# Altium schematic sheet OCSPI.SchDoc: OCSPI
size A4; Date: Not used; ApprovedBy: Not used; CheckedBy: Not used; Author: Not used; CompanyName: STMicroelectronics; DrawnBy: Not used; Engineer: Not used; Organization: Not used; Address1: Not used; Address2: Not used; Address3: Not used; Address4: Not used; DocumentNumber: Not used; Revision: Not used; SheetNumber: 8; SheetTotal: 23
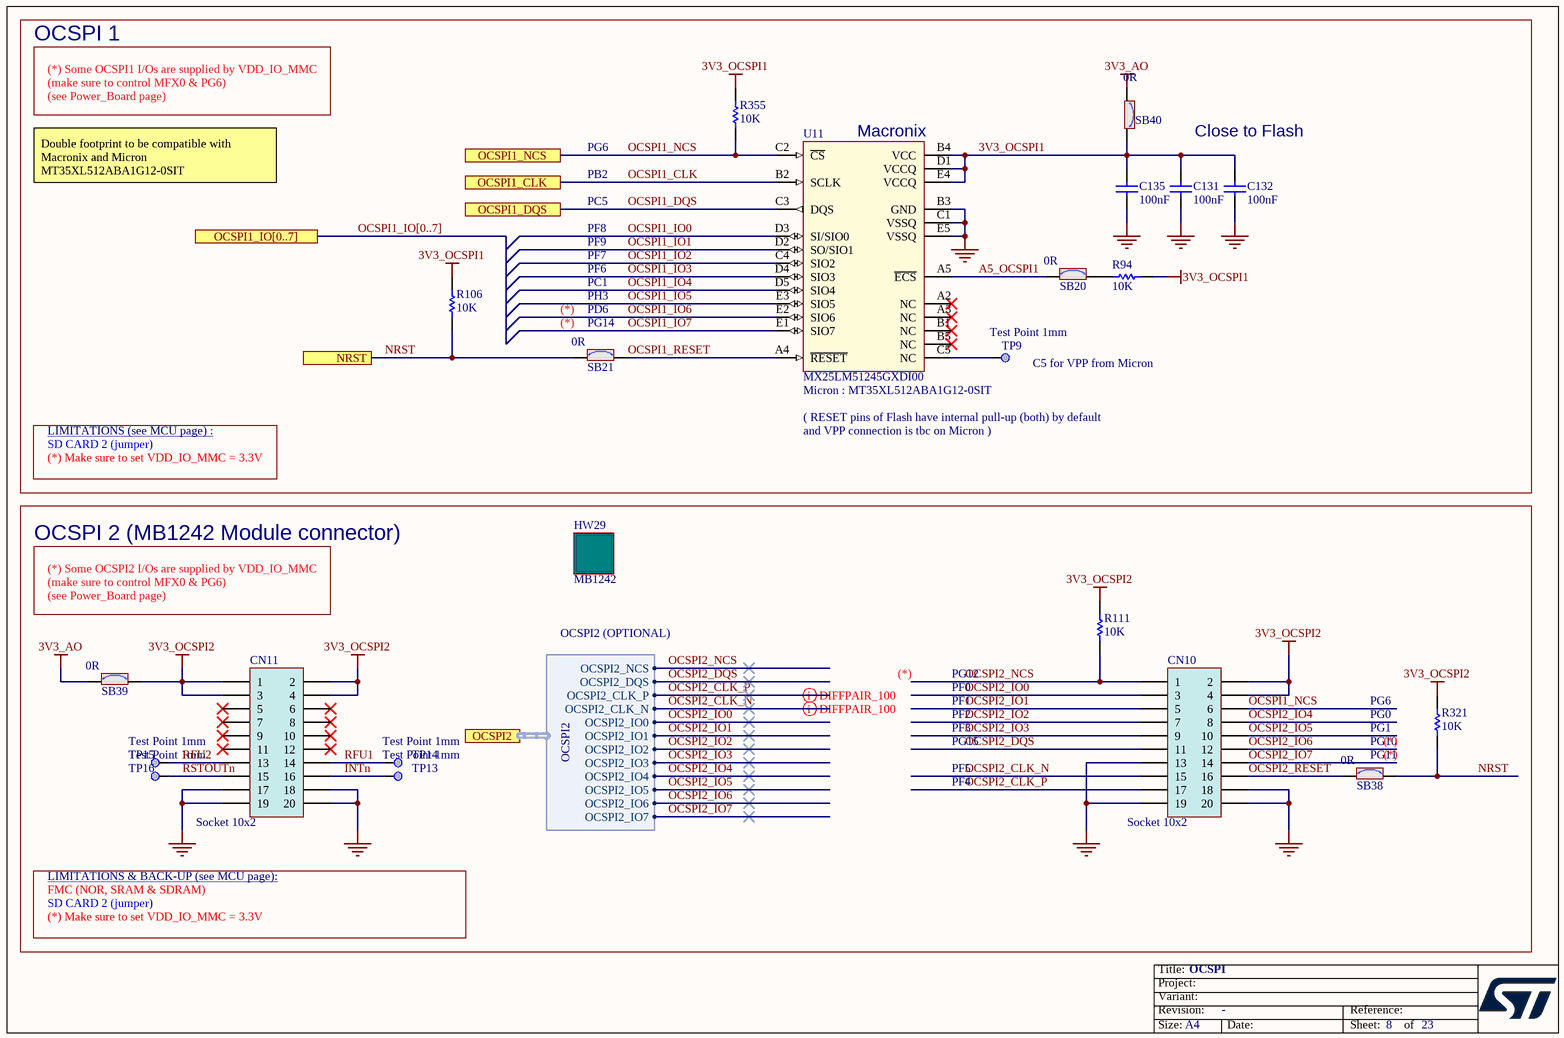
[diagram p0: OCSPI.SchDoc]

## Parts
C131  value 100nF  [C0402]  (hidden comment: Capacitor)
C132  value 100nF  [C0402]  (hidden comment: Capacitor)
C135  value 100nF  [C0402]  (hidden comment: Capacitor)
CN10  Socket 10x2  [CON_SAMTEC_ERF8-010-050-S-DV-TR]
CN11  Socket 10x2  [CON_SAMTEC_ERF8-010-050-S-DV-TR]
HW29  value MB1242  [MOD_ERM8_BGA24-OCTAL-SPI_MB1242]  (hidden comment: Daughter_Board)
R94  value 10K  [R0402]  (hidden comment: Resistor)
R106  value 10K  [R0402]  (hidden comment: Resistor)
R111  value 10K  [R0402]  (hidden comment: Resistor)
R321  value 10K  [R0402]  (hidden comment: Resistor)
R355  value 10K  [R0402]  (hidden comment: Resistor)
SB20  value 0R  [SOLDER-BRIDGE_R0603-0R]  (hidden comment: SB_ON)
SB21  value 0R  [SOLDER-BRIDGE_R0603-0R]  (hidden comment: SB_ON)
SB38  value 0R  [SOLDER-BRIDGE_R0603-0R]  (hidden comment: SB_ON)
SB39  value 0R  [SOLDER-BRIDGE_R0603-0R]  (hidden comment: SB_ON)
SB40  value 0R  [SOLDER-BRIDGE_R0603-0R]  (hidden comment: SB_ON)
TP9  value Test Point 1mm  [TP_SMD_1MM]  (hidden comment: Test Point)  (no BOM)
TP13  value Test Point 1mm  [TP_SMD_1MM]  (hidden comment: Test Point)  (no BOM)
TP14  value Test Point 1mm  [TP_SMD_1MM]  (hidden comment: Test Point)  (no BOM)
TP15  value Test Point 1mm  [TP_SMD_1MM]  (hidden comment: Test Point)  (no BOM)
TP16  value Test Point 1mm  [TP_SMD_1MM]  (hidden comment: Test Point)  (no BOM)
U11  MX25LM51245GXDI00  [ICC_BGA24_5X5-BALL-ARRAY_6X8_P1]

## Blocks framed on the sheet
OCSPI 1: C131 C132 C135 R94 R106 R355 SB20 SB21 SB40 TP9 U11
OCSPI 2 (MB1242 Module connector): CN10 CN11 HW29 R111 R321 SB38 SB39 TP13-TP16

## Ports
NRST, OCSPI1_CLK, OCSPI1_DQS, OCSPI1_IO[0..7], OCSPI1_NCS, OCSPI2 (harness OCSPI2)

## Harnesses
OCSPI2: OCSPI2_NCS, OCSPI2_DQS, OCSPI2_CLK_P, OCSPI2_CLK_N, OCSPI2_IO0, OCSPI2_IO1, OCSPI2_IO2, OCSPI2_IO3, OCSPI2_IO4, OCSPI2_IO5, OCSPI2_IO6, OCSPI2_IO7

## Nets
3V3_AO: SB39.2 SB40.1
3V3_OCSPI1: C131.2 C132.2 C135.2 R94.2 R106.1 R355.1 SB40.2 U11.B4(VCC) U11.D1(VCCQ) U11.E4(VCCQ)
3V3_OCSPI2: CN10.2 CN10.4 CN11.1 CN11.2 CN11.3 CN11.4 R111.1 R321.1 SB39.1
GND: C131.1 C132.1 C135.1 CN10.13 CN10.18 CN10.19 CN10.20 CN11.17 CN11.18 CN11.19 CN11.20 U11.B3(GND) U11.C1(VSSQ) U11.E5(VSSQ)
A5_OCSPI1: SB20.1 U11.A5(~{ECS})
INTn: CN11.16 TP13.1
NRST: R106.2 R321.2 SB21.1 SB38.1 ; port NRST
OCSPI1_CLK: U11.B2(SCLK) ; port OCSPI1_CLK
OCSPI1_DQS: U11.C3(DQS) ; port OCSPI1_DQS
OCSPI1_IO0: U11.D3(SI/SIO0)
OCSPI1_IO1: U11.D2(SO/SIO1)
OCSPI1_IO2: U11.C4(SIO2)
OCSPI1_IO3: U11.D4(SIO3)
OCSPI1_IO4: U11.D5(SIO4)
OCSPI1_IO5: U11.E3(SIO5)
OCSPI1_IO6: U11.E2(SIO6)
OCSPI1_IO7: U11.E1(SIO7)
OCSPI1_NCS: CN10.6 R355.2 U11.C2(~{CS}) ; port OCSPI1_NCS
OCSPI1_RESET: SB21.2 U11.A4(~{RESET})
OCSPI2_CLK_N: CN10.15 ; port OCSPI2.OCSPI2_CLK_N
OCSPI2_CLK_P: CN10.17 ; port OCSPI2.OCSPI2_CLK_P
OCSPI2_DQS: CN10.11 ; port OCSPI2.OCSPI2_DQS
OCSPI2_IO0: CN10.3 ; port OCSPI2.OCSPI2_IO0
OCSPI2_IO1: CN10.5 ; port OCSPI2.OCSPI2_IO1
OCSPI2_IO2: CN10.7 ; port OCSPI2.OCSPI2_IO2
OCSPI2_IO3: CN10.9 ; port OCSPI2.OCSPI2_IO3
OCSPI2_IO4: CN10.8 ; port OCSPI2.OCSPI2_IO4
OCSPI2_IO5: CN10.10 ; port OCSPI2.OCSPI2_IO5
OCSPI2_IO6: CN10.12 ; port OCSPI2.OCSPI2_IO6
OCSPI2_IO7: CN10.14 ; port OCSPI2.OCSPI2_IO7
OCSPI2_NCS: CN10.1 R111.2 ; port OCSPI2.OCSPI2_NCS
OCSPI2_RESET: CN10.16 SB38.2
RFU1: CN11.14 TP14.1
RFU2: CN11.13 TP15.1
RSTOUTn: CN11.15 TP16.1
NetR94_1: R94.1 SB20.2
NetTP9_1: TP9.1 U11.C5(NC)

Not connected (* = marked no-connect by the designer): CN11 5* 6* 7* 8* 9* 10* 11* 12*; U11 A2(NC)* A3(NC)* B1(NC)* B5(NC)*

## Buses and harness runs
bus OCSPI1_IO[0..7] = port OCSPI1_IO[0..7]

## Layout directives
differential pair: OCSPI2_CLK_N, OCSPI2_CLK_P

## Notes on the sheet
- (*) Some OCSPI1 I/Os are supplied by VDD_IO_MMC
  (make sure to control MFX0 & PG6)
  (see Power_Board page)
- Double footprint to be compatible with Macronix and Micron MT35XL512ABA1G12-0SIT
- PB2
- PG6
- (near U11) Macronix
- Close to Flash
- PF8
- PC5
- PF9
- (near SB21) (*)
- PF6
- PH3
- PC1
- (near SB21) PD6
- PF7
- (near SB21) PG14
- (near TP9) C5 for VPP from Micron
- LIMITATIONS (see MCU page) :
- SD CARD 2 (jumper)
- ( RESET pins of Flash have internal pull-up (both) by default
- and VPP connection is tbc on Micron )
- Micron : MT35XL512ABA1G12-0SIT
- (*) Make sure to set VDD_IO_MMC = 3.3V
- (*) Some OCSPI2 I/Os are supplied by VDD_IO_MMC
  (make sure to control MFX0 & PG6)
  (see Power_Board page)
- OCSPI2 (OPTIONAL)
- (*)
- PF0
- PF2
- PF1
- PG12
- PG0
- PF3
- PF4
- PF5
- PG15
- (near SB38) PG1
- (near SB38) PG10
- (near SB38) PG11
- (near SB38) (*)
- LIMITATIONS & BACK-UP (see MCU page):
- FMC (NOR, SRAM & SDRAM)

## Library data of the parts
C131 C132 C135 = MCD-00006: Capacitor, MLCC, 100nF, 16V, X7R, 10%, 0402, T=0.5mm; Manufacturer_Part_Number: CC0402KRX7R7BB104; Manufacturer: YAGEO; Alternate_Manufacturer_Part_Number: GCM155R71C104KA55D; Alternate_Manufacturer: MURATA; Part_Preference: Recommended; Partial_Alternate_Internal_Part_Number: MCD-03299; Provided_By: SUBCO; ECCN_US: EAR99; ECCN_EU: NEC; Component_Country_Of_Origin: China; ID: 2474; Order_Code_RS: 9402047; ShowFields: YES
CN10 CN11 = MCD-00675: Socket High Speed, 10x2, 0.8mm, Center Strip Contacts, VR, SMT, Height 5.33 mm; Part_Type: Connector; Manufacturer_Part_Number: ERF8-010-05.0-S-DV-TR; Manufacturer: SAMTEC; Part_Preference: Recommended; Provided_By: SUBCO; ECCN_US: EAR99; ECCN_EU: NEC; Component_Country_Of_Origin: China, Costa Rica, Malaysia, USA, Vietnam; ID: 3071; Order_Code_RS: 766-8868; ShowFields: YES
HW29 = MCD-01033: MB1242 - ERM8 BGA24 Octal SPI module; Part_Type: Misc; Manufacturer: STMICROELECTRONICS; Part_Preference: Recommended; Provided_By: SUBCO with ST control; Component_Country_Of_Origin: Unknown; ID: 2990; ShowFields: YES
R94 R106 R111 R321 R355 = MCD-00053: Resistor,10K,0402,1%,1/16W; Manufacturer_Part_Number: RC0402FR-0710KL; Manufacturer: YAGEO; BMS_Part_Number: 9131590; Part_Preference: Recommended; Provided_By: SUBCO; ECCN_US: EAR99; ECCN_EU: NEC; Component_Country_Of_Origin: China; ID: 2539; Order_Code_RS: 9239359; ShowFields: YES
SB20 SB21 SB38-SB40 = MCD-00071: Solder Bridge ON; Part_Type: Resistor; Manufacturer_Part_Number: RC0603JR-070RL; Manufacturer: YAGEO; Manufacturer_HQ_COO: Unknown; Part_Preference: Recommended; Provided_By: SUBCO; Component_Country_Of_Origin: China; ID: 2521; Order_Code_RS: 199-5647; ShowFields: YES
TP9 TP13-TP16 = MCD-00074: Test Point 1mm; Part_Type: Misc; Part_Preference: Recommended; Component_Country_Of_Origin: Unknown; ID: 2518; ShowFields: YES
U11 = MCD-00246: Memory,Octo-SPI-NOR,512Mb,2048x16,133MHz,3V,DTR,BGA24, CMOS MXSMIO; Part_Type: IC; Manufacturer: MACRONIX; Part_Preference: Recommended; Provided_By: SUBCO; ECCN_US: 3A991.b.1.a; Component_Country_Of_Origin: Taiwan°; ID: 2623; ShowFields: YES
